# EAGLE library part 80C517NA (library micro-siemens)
MICROPROCESSOR/PERIPHERAL DEVICE
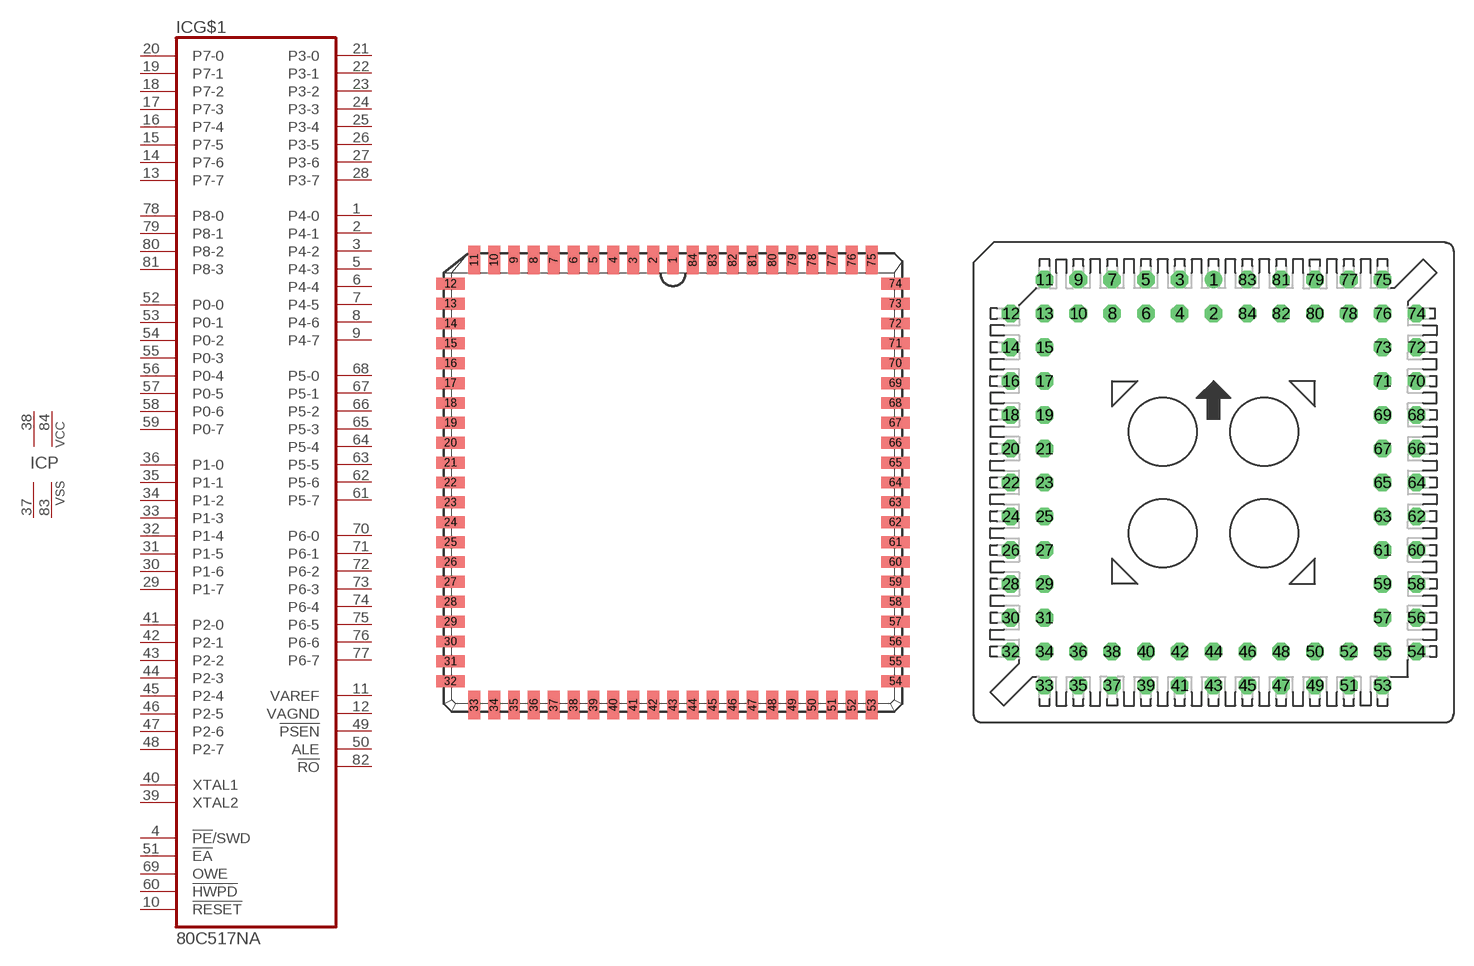
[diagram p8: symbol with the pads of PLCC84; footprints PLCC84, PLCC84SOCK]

Designator prefix IC; gates G$1=80C517NA P=2VCC2VSS

## 80C517NA (OC_FARNELL: unknown; OC_NEWARK: unknown)  [PLCC84]
1  G$1:P4-0
2  G$1:P4-1
3  G$1:P4-2
4  G$1:!PE!/SWD  in
5  G$1:P4-3
6  G$1:P4-4
7  G$1:P4-5
8  G$1:P4-6
9  G$1:P4-7
10  G$1:!RESET  in
11  G$1:VAREF  pas
12  G$1:VAGND  pas
13  G$1:P7-7  in
14  G$1:P7-6  in
15  G$1:P7-5  in
16  G$1:P7-4  in
17  G$1:P7-3  in
18  G$1:P7-2  in
19  G$1:P7-1  in
20  G$1:P7-0  in
21  G$1:P3-0
22  G$1:P3-1
23  G$1:P3-2
24  G$1:P3-3
25  G$1:P3-4
26  G$1:P3-5
27  G$1:P3-6
28  G$1:P3-7
29  G$1:P1-7
30  G$1:P1-6
31  G$1:P1-5
32  G$1:P1-4
33  G$1:P1-3
34  G$1:P1-2
35  G$1:P1-1
36  G$1:P1-0
37  P:VSS  pwr
38  P:VCC  pwr
39  G$1:XTAL2  pas
40  G$1:XTAL1  pas
41  G$1:P2-0
42  G$1:P2-1
43  G$1:P2-2
44  G$1:P2-3
45  G$1:P2-4
46  G$1:P2-5
47  G$1:P2-6
48  G$1:P2-7
49  G$1:!PSEN  out
50  G$1:ALE  out
51  G$1:!EA  in
52  G$1:P0-0
53  G$1:P0-1
54  G$1:P0-2
55  G$1:P0-3
56  G$1:P0-4
57  G$1:P0-5
58  G$1:P0-6
59  G$1:P0-7
60  G$1:!HWPD  in
61  G$1:P5-7
62  G$1:P5-6
63  G$1:P5-5
64  G$1:P5-4
65  G$1:P5-3
66  G$1:P5-2
67  G$1:P5-1
68  G$1:P5-0
69  G$1:OWE  in
70  G$1:P6-0
71  G$1:P6-1
72  G$1:P6-2
73  G$1:P6-3
74  G$1:P6-4
75  G$1:P6-5
76  G$1:P6-6
77  G$1:P6-7
78  G$1:P8-0  in
79  G$1:P8-1  in
80  G$1:P8-2  in
81  G$1:P8-3  in
82  G$1:!RO  out
83  P:VSS  pwr
84  P:VCC  pwr

## 80C517NASOC (OC_FARNELL: unknown; OC_NEWARK: unknown)  [PLCC84SOCK]
Pads as for PLCC84

## Footprint PLCC84 (pad centres in mm)
PLASTIC LEADED CHIP CARRIER square
smd 0.76 x 1.8: 1 0,14.21; 2 -1.27,14.21; 3 -2.54,14.21; 4 -3.81,14.21; 5 -5.08,14.21; 6 -6.35,14.21; 7 -7.62,14.21; 8 -8.89,14.21; 9 -10.16,14.21; 10 -11.43,14.21; 11 -12.7,14.21; 33 -12.7,-14.21; 34 -11.43,-14.21; 35 -10.16,-14.21; 36 -8.89,-14.21; 37 -7.62,-14.21; 38 -6.35,-14.21; 39 -5.08,-14.21; 40 -3.81,-14.21; 41 -2.54,-14.21; 42 -1.27,-14.21; 43 0,-14.21; 44 1.27,-14.21; 45 2.54,-14.21; 46 3.81,-14.21; 47 5.08,-14.21; 48 6.35,-14.21; 49 7.62,-14.21; 50 8.89,-14.21; 51 10.16,-14.21; 52 11.43,-14.21; 53 12.7,-14.21; 75 12.7,14.21; 76 11.43,14.21; 77 10.16,14.21; 78 8.89,14.21; 79 7.62,14.21; 80 6.35,14.21; 81 5.08,14.21; 82 3.81,14.21; 83 2.54,14.21; 84 1.27,14.21
smd 1.8 x 0.76: 12 -14.21,12.7; 13 -14.21,11.43; 14 -14.21,10.16; 15 -14.21,8.89; 16 -14.21,7.62; 17 -14.21,6.35; 18 -14.21,5.08; 19 -14.21,3.81; 20 -14.21,2.54; 21 -14.21,1.27; 22 -14.21,0; 23 -14.21,-1.27; 24 -14.21,-2.54; 25 -14.21,-3.81; 26 -14.21,-5.08; 27 -14.21,-6.35; 28 -14.21,-7.62; 29 -14.21,-8.89; 30 -14.21,-10.16; 31 -14.21,-11.43; 32 -14.21,-12.7; 54 14.21,-12.7; 55 14.21,-11.43; 56 14.21,-10.16; 57 14.21,-8.89; 58 14.21,-7.62; 59 14.21,-6.35; 60 14.21,-5.08; 61 14.21,-3.81; 62 14.21,-2.54; 63 14.21,-1.27; 64 14.21,0; 65 14.21,1.27; 66 14.21,2.54; 67 14.21,3.81; 68 14.21,5.08; 69 14.21,6.35; 70 14.21,7.62; 71 14.21,8.89; 72 14.21,10.16; 73 14.21,11.43; 74 14.21,12.7

## Footprint PLCC84SOCK (pad centres in mm)
PLCC 84 socked
drill 0.813 round: 1 0,15.24
drill 0.813 octagon: 2 0,12.7; 3 -2.54,15.24; 4 -2.54,12.7; 5 -5.08,15.24; 6 -5.08,12.7; 7 -7.62,15.24; 8 -7.62,12.7; 9 -10.16,15.24; 10 -10.16,12.7; 11 -12.7,15.24; 12 -15.24,12.7; 13 -12.7,12.7; 14 -15.24,10.16; 15 -12.7,10.16; 16 -15.24,7.62; 17 -12.7,7.62; 18 -15.24,5.08; 19 -12.7,5.08; 20 -15.24,2.54; 21 -12.7,2.54; 22 -15.24,0; 23 -12.7,0; 24 -15.24,-2.54; 25 -12.7,-2.54; 26 -15.24,-5.08; 27 -12.7,-5.08; 28 -15.24,-7.62; 29 -12.7,-7.62; 30 -15.24,-10.16; 31 -12.7,-10.16; 32 -15.24,-12.7; 33 -12.7,-15.24; 34 -12.7,-12.7; 35 -10.16,-15.24; 36 -10.16,-12.7; 37 -7.62,-15.24; 38 -7.62,-12.7; 39 -5.08,-15.24; 40 -5.08,-12.7; 41 -2.54,-15.24; 42 -2.54,-12.7; 43 0,-15.24; 44 0,-12.7; 45 2.54,-15.24; 46 2.54,-12.7; 47 5.08,-15.24; 48 5.08,-12.7; 49 7.62,-15.24; 50 7.62,-12.7; 51 10.16,-15.24; 52 10.16,-12.7; 53 12.7,-15.24; 54 15.24,-12.7; 55 12.7,-12.7; 56 15.24,-10.16; 57 12.7,-10.16; 58 15.24,-7.62; 59 12.7,-7.62; 60 15.24,-5.08; 61 12.7,-5.08; 62 15.24,-2.54; 63 12.7,-2.54; 64 15.24,0; 65 12.7,0; 66 15.24,2.54; 67 12.7,2.54; 68 15.24,5.08; 69 12.7,5.08; 70 15.24,7.62; 71 12.7,7.62; 72 15.24,10.16; 73 12.7,10.16; 74 15.24,12.7; 75 12.7,15.24; 76 12.7,12.7; 77 10.16,15.24; 78 10.16,12.7; 79 7.62,15.24; 80 7.62,12.7; 81 5.08,15.24; 82 5.08,12.7; 83 2.54,15.24; 84 2.54,12.7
